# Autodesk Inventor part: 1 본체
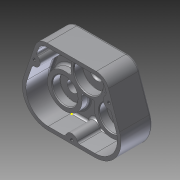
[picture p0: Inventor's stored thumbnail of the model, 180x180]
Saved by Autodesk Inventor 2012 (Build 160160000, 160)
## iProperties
Created: 2014-12
Part Number: 1 본체
Material: Default
Document SubType Name: Modeling
Designer: Owner
Density: 1 g/cm^3
Author: Owner
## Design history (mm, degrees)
sketch "스케치1"
  geometry: L1 (-47, 36)-(47, 36); L2 (0, 36)-(0, 0); L3 (0, 0)-(-32.527, -32.527); L4 (0, 0)-(32.527, -32.527); L5 (0, 0)-(0, -46); L6 (-32.527, -68.527)-(32.527, -68.527); L7 (-47, 36)-(-66.565, -20.803); L8 (47, 36)-(66.565, -20.803); A1 r 46 centre (0, 0) between (-32.527, -32.527) and (32.527, -32.527); A2 r 36 centre (-32.527, -32.527) between (-32.527, -68.527) and (-66.565, -20.803); A3 r 36 centre (32.527, -32.527) between (32.527, -68.527) and (66.565, -20.803); 1 further point
  constraints: 16 end point, 7 point on circle, 4 coincident, 4 tangent, 3 centre point, 1 collinear, 1 equal radius, 1 horizontal, 1 midpoint, 1 perpendicular
  dimensions: "d0" = 94 distance of L1.start L1.end; "d2" = 36 distance of point (0, 0) L2.start; "d3" = 92 diameter of A1; "d5" = 45 deg angle of L3 L5; "d6" = 45 deg angle of L4 L5; "d7" = 72 diameter of A2
extrude "돌출1" new body sketch "스케치1" distance "d8" = 44; taper "d9" = 0 deg
fillet "모깎기1" dims "d10" = 18
feature "쉘1" dims "d11" = 5
sketch "스케치2"
  geometry: L1 (46.453, 22.233)-(61.837, -22.432) reference; L2 (32.527, -63.527)-(-32.527, -63.527) reference; L3 (-61.837, -22.432)-(-46.453, 22.233) reference; L4 (34.162, 36)-(-34.162, 36) reference; A1 r 8 centre (51.7, 7) between (49.095, 14.564) and (54.305, -0.564); A2 r 8 centre (-51.7, 7) between (-54.305, -0.564) and (-49.095, 14.564); A3 r 8 centre (0, -63.527) between (8, -63.527) and (-8, -63.527); 4 further points
  constraints: 8 point on line, 6 point on circle, 3 centre point, 3 coincident, 1 midpoint
  dimensions: "d12" = 29 distance from line of point (51.7, 7) L4; "d14" = 8 radius of A1; "d15" = 29 distance from line of point (-51.7, 7) L4; "d16" = 16 diameter of A2; "d17" = 16 diameter of A3
extrude "돌출2" join sketch "스케치2" distance "d18" = 34; taper "d19" = 0 deg
sketch "스케치6"
  geometry: C1 r 20 at (-32.527, -32.527); C2 r 20 at (32.527, -32.527); A1 r 36 centre (-32.527, -32.527) between (-66.565, -20.803) and (-32.527, -68.527) reference; A2 r 36 centre (32.527, -32.527) between (32.527, -68.527) and (66.565, -20.803) reference; 1 further point
  constraints: 2 centre point, 2 coincident
  dimensions: "d20" = 40 diameter of C1; "d22" = 40 diameter of C2
extrude "돌출3" join sketch "스케치6" distance "d23" = 7; taper "d24" = -10 deg
hole "구멍1" diameter "d27" = 30; stored, may be unused: countersink angle "d31" = 90 deg, drill point angle "d33" = 0 deg; dims "d25" = 10, "d26" = 10, "d28" = 6, "d29" = 4, "d30" = 2, "d32" = 7
hole "구멍2" diameter "d36" = 30; stored, may be unused: countersink angle "d40" = 90 deg, drill point angle "d42" = 0 deg; dims "d34" = 10, "d35" = 10, "d37" = 6, "d38" = 4, "d39" = 2, "d41" = 7
node "작업 평면1"
sketch "스케치15"
  geometry: C1 r 24 at (34.162, -31); C2 r 24 at (1.635, -63.527); C3 r 24 at (66.689, -63.527); A1 r 31 centre (1.635, -63.527) between (-27.675, -53.432) and (1.635, -94.527) reference; A2 r 31 centre (66.689, -63.527) between (66.689, -94.527) and (95.999, -53.432) reference; 1 further point
  constraints: 3 centre point, 3 coincident
  dimensions: "d53" = 48 diameter of C1; "d54" = 48 diameter of C2; "d55" = 48 diameter of C3
extrude "돌출8" join sketch "스케치15" distance "d58" = 16; taper "d59" = 0 deg
hole "구멍3" diameter "d62" = 15.5; stored, may be unused: countersink angle "d66" = 90 deg, drill point angle "d68" = 0 deg; dims "d60" = 10, "d61" = 10, "d63" = 6, "d64" = 4, "d65" = 2, "d67" = 10
hole "구멍4" diameter "d71" = 15.5; stored, may be unused: countersink angle "d75" = 90 deg, drill point angle "d77" = 0 deg; dims "d69" = 10, "d70" = 10, "d72" = 6, "d73" = 4, "d74" = 2, "d76" = 10
hole "구멍5" diameter "d80" = 35; stored, may be unused: countersink angle "d84" = 90 deg, drill point angle "d86" = 0 deg; dims "d78" = 10, "d79" = 10, "d81" = 6, "d82" = 4, "d83" = 2, "d85" = 11
hole "구멍6" diameter "d89" = 35; stored, may be unused: countersink angle "d93" = 90 deg, drill point angle "d95" = 0 deg; dims "d87" = 10, "d88" = 10, "d90" = 6, "d91" = 4, "d92" = 2, "d94" = 11
sketch "스케치24"
  geometry: C1 r 20 at (34.162, -31); A1 r 24 centre (34.162, -31) between (22.746, -52.111) and (45.578, -52.111) reference
  constraints: 1 centre point, 1 coincident
  dimensions: "d97" = 40 diameter of C1
extrude "돌출9" cut sketch "스케치24" distance "d98" = 12; taper "d99" = 0 deg
hole "구멍7" diameter "d102" = 20; stored, may be unused: countersink angle "d106" = 90 deg, drill point angle "d108" = 0 deg; dims "d100" = 10, "d101" = 10, "d103" = 6, "d104" = 4, "d105" = 2, "d107" = 3
sketch "스케치26"
  geometry: L1 (-12.291, -8.767)-(-27.675, -53.432) reference; L2 (1.635, -94.527)-(66.689, -94.527) reference; L3 (95.999, -53.432)-(80.615, -8.767) reference; L4 (68.324, 0)-(0, 0) reference; A1 r 24 centre (34.162, -31) between (55.273, -42.416) and (13.051, -42.416) reference; A2 r 24 centre (66.689, -63.527) between (45.578, -52.111) and (55.273, -42.416) reference; A3 r 24 centre (34.162, -31) between (22.746, -52.111) and (45.578, -52.111) reference; A4 r 24 centre (1.635, -63.527) between (13.051, -42.416) and (22.746, -52.111) reference; A5 r 13 centre (0, -13) between (0, 0) and (-12.291, -8.767) reference; A6 r 31 centre (1.635, -63.527) between (-27.675, -53.432) and (1.635, -94.527) reference; A7 r 31 centre (66.689, -63.527) between (66.689, -94.527) and (95.999, -53.432) reference; A8 r 13 centre (68.324, -13) between (80.615, -8.767) and (68.324, 0) reference
extrude "돌출10" join sketch "스케치26" distance "d109" = 5; taper "d110" = 0 deg
sketch "스케치28"
  geometry: A1 r 8 centre (51.7, 7) between (49.095, 14.564) and (54.305, -0.564) reference; A2 r 8 centre (0, -63.527) between (8, -63.527) and (-8, -63.527) reference; A3 r 8 centre (-51.7, 7) between (-54.305, -0.564) and (-49.095, 14.564) reference; 4 further points
  constraints: 3 coincident
hole "구멍8" sketch "스케치28" at (51.7, 7), (0, -63.527), (-51.7, 7) diameter "d111" = 4.134; stored, may be unused: countersink angle "d115" = 90 deg, drill point angle "d117" = 118 deg; dims "d112" = 20, "d113" = 4, "d114" = 2, "d116" = 23
sketch "스케치29"
  geometry: L1 (-34.162, 36)-(34.162, 36) reference; 2 further points
  constraints: 1 vertical alignment, 1 other
  dimensions: "d118" = 30 distance from line of point (0, 6) L1
feature "엠보싱1" sketch "스케치29" dims "d0" = 94, "d2" = 36, "d3" = 92, "d5" = 45 deg, "d6" = 45 deg, "d7" = 72, "d119" = 1, "d120" = 0
chamfer "모따기1" distance "d121" = 1; stored, may be unused: second distance "d122" = 2, angle "d123" = 45 deg
chamfer "모따기2" distance "d124" = 1; stored, may be unused: second distance "d125" = 2, angle "d126" = 45 deg
fillet "모깎기2" dims "d127" = 3
fillet "모깎기3" dims "d128" = 0.3
fillet "모깎기4" dims "d129" = 3
fillet "모깎기5" dims "d130" = 0.1
fillet "모깎기6" dims "d131" = 0.3
fillet "모깎기7" dims "d132" = 3
fillet "모깎기8" dims "d133" = 3
fillet "모깎기9" dims "d134" = 3
fillet "모깎기10" dims "d135" = 3
fillet "모깎기11" dims "d136" = 3
sketch "스케치31"
  geometry: 1 further point
node "솔리드1"
other parameters: "d13" = 16, "d52" = -36
